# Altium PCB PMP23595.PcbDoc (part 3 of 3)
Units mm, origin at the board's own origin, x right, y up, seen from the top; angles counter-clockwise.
Board outline 121.92 x 78.74 mm, 6 copper layers (Layer 1, GND 1, Layer 3, Layer 4, GND 2, Layer 6), stack 2.208 mm thick; 236 components, 76 nets, 570 pads, 735 vias.
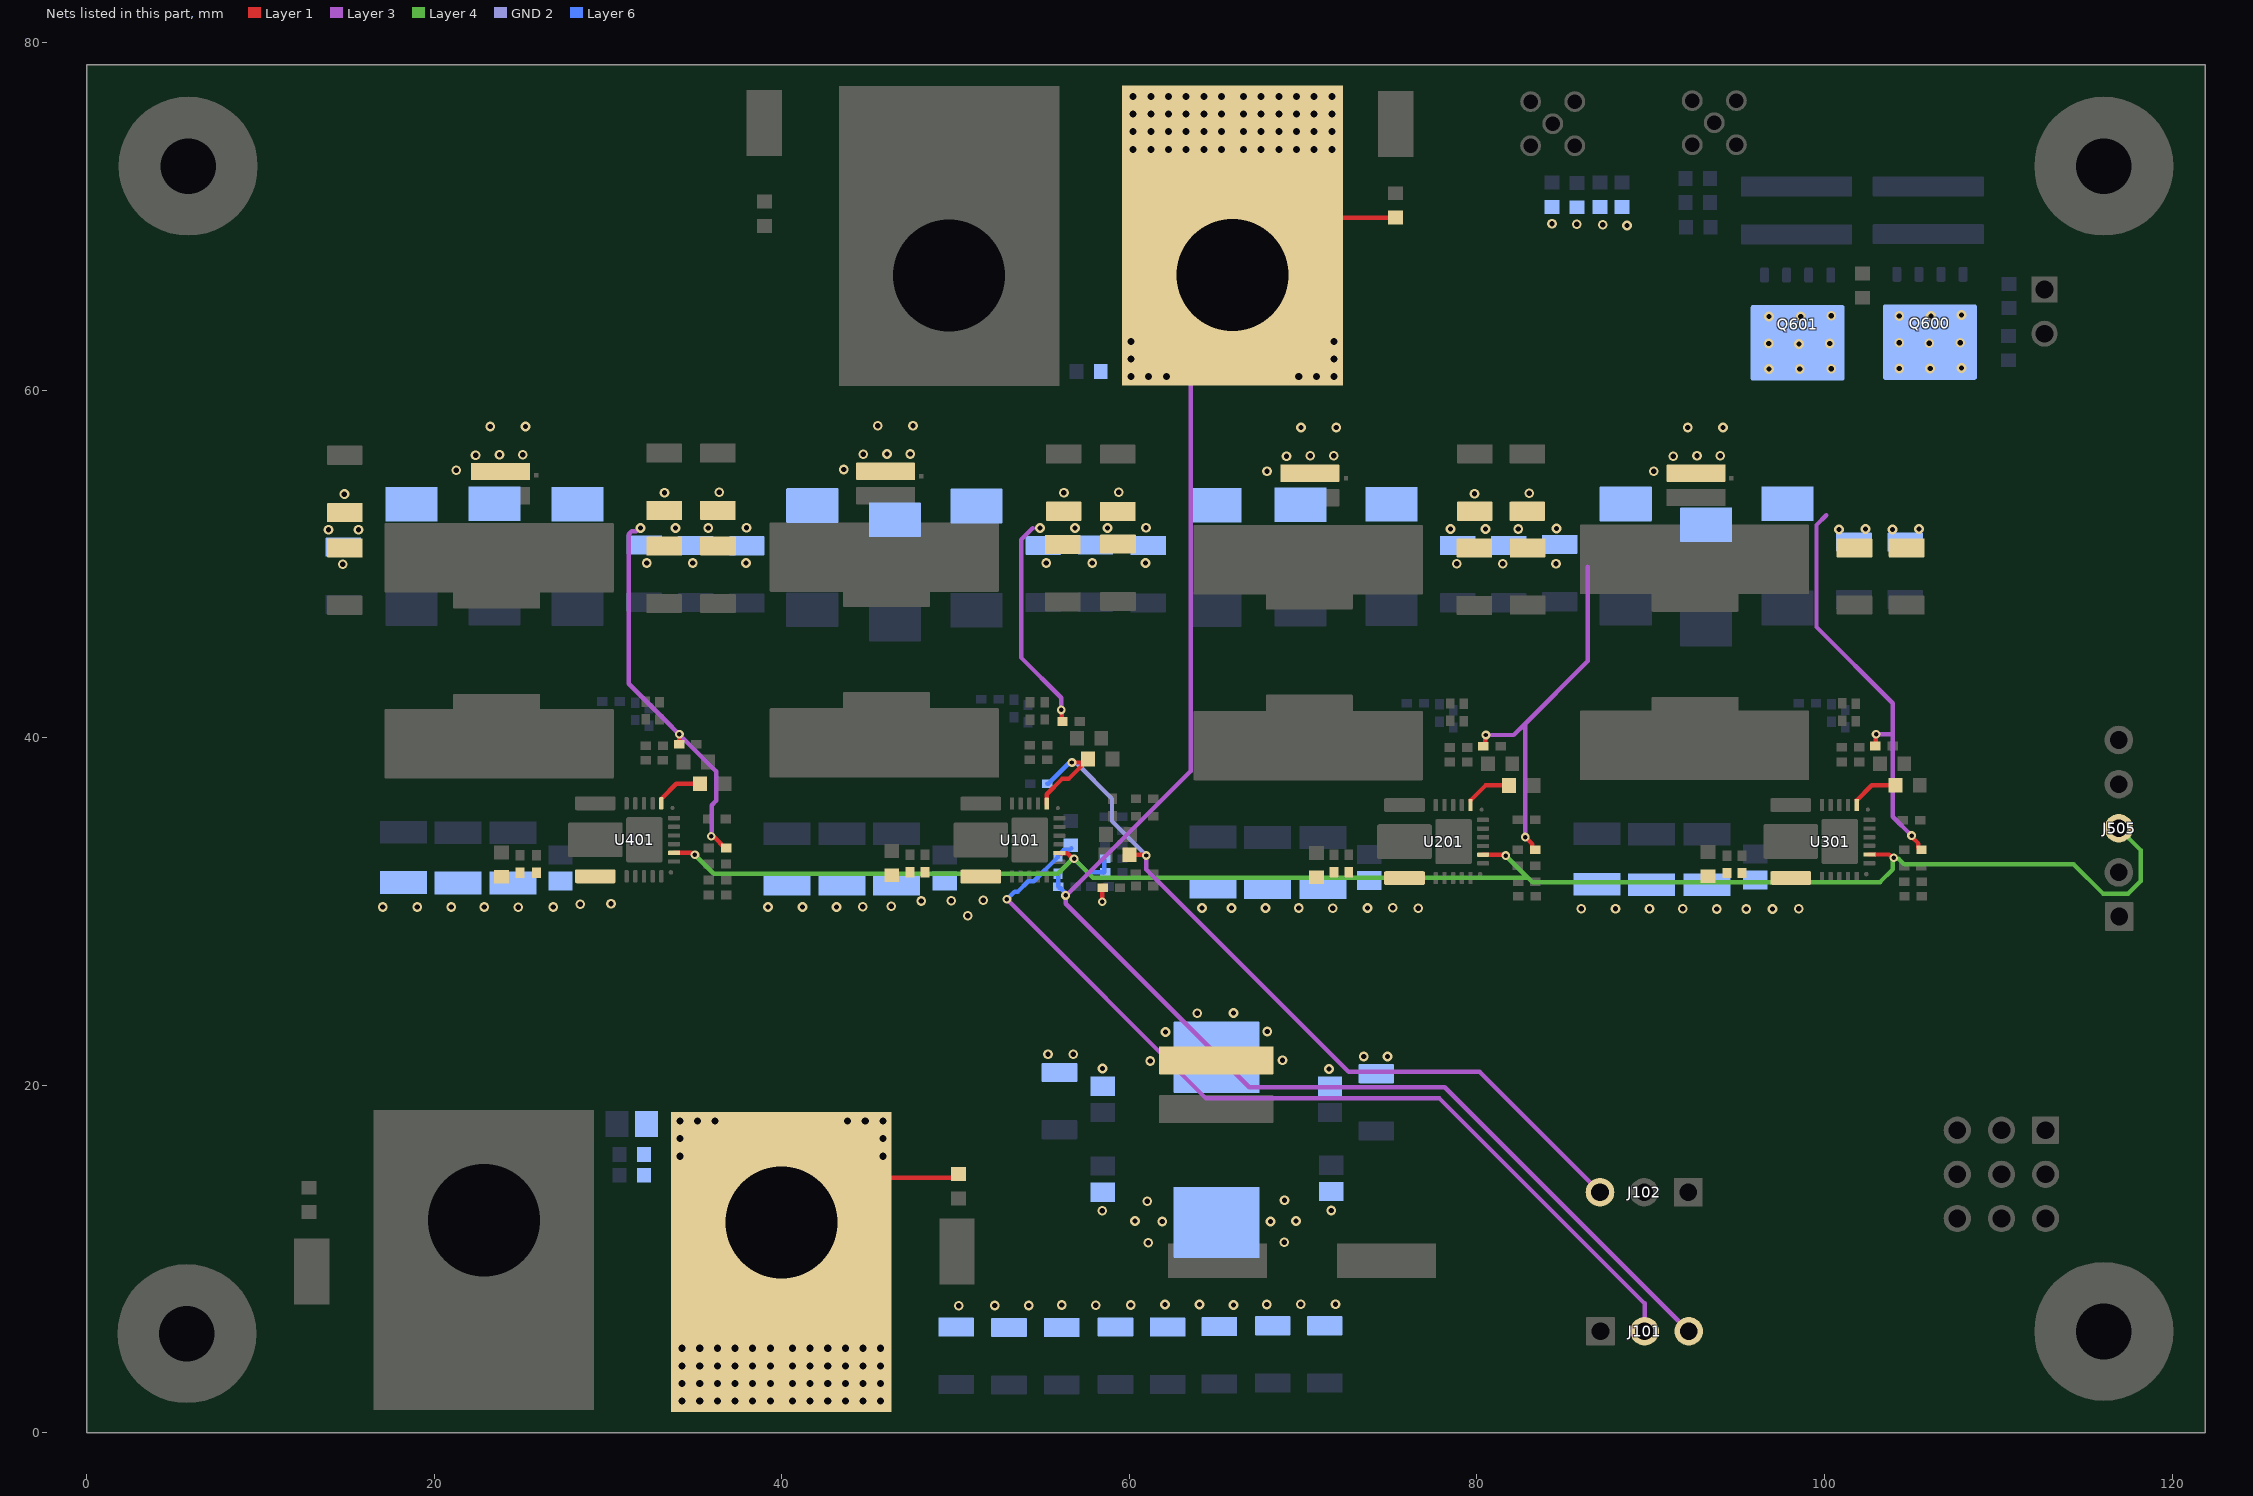
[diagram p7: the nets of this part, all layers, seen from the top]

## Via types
v1: diameter 0.559, hole 0.305, Layer 1 to Layer 6, tented both sides, 328 vias
v2: diameter 0.813, hole 0.406, Layer 1 to Layer 6, 232 vias
v3: diameter 0.508, hole 0.254, Layer 1 to Layer 6, tented both sides, 72 vias
v4: diameter 0.5, hole 0.2, Layer 1 to Layer 6, tented both sides, 72 vias
v5: diameter 0.559, hole 0.305, Layer 1 to Layer 6, 24 vias
v6: diameter 5.8, hole 2.8, Layer 1 to Layer 6, 7 vias

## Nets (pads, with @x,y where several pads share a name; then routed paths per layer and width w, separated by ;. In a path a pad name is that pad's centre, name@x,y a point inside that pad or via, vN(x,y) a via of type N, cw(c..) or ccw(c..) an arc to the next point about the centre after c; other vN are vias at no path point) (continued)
VBAT+: C500.2 C501.1 C502.1 C503.2 C504.2 C505.2 C506.2 C507.2 C508.2 C509.2 C510.2 C511.1 C512.1 L500.1 R500.2 T500.1 | length 9.7
  Layer 1 w0.254: T500.1@40.564,14.681 49.948,14.681 R500.2@50.165,14.899
  other v1: 50.188,7.32 52.254,7.338 54.21,7.338 58.075,7.352 56.115,7.363 60.077,7.363 65.995,7.363 62.058,7.388 64.04,7.388 67.9,7.388 69.86,7.403 71.863,7.414 61.085,10.953 68.91,10.973 61.898,12.172 68.121,12.172 60.323,12.197 69.594,12.197 58.443,12.781 71.626,12.807 61.034,13.34 68.933,13.391
  other v2: 34.265,1.829 35.281,1.829 36.297,1.829 37.313,1.829 38.329,1.829 39.345,1.829 40.615,1.829 41.631,1.829 42.647,1.829 43.663,1.829 44.679,1.829 45.695,1.829 34.265,2.845 35.281,2.845 36.297,2.845 37.313,2.845 38.329,2.845 39.345,2.845 40.615,2.845 41.631,2.845 42.647,2.845 43.663,2.845 44.679,2.845 45.695,2.845 34.265,3.861 35.281,3.861 36.297,3.861 37.313,3.861 38.329,3.861 39.345,3.861 40.615,3.861 41.631,3.861 42.647,3.861 43.663,3.861 44.679,3.861 45.695,3.861 34.265,4.877 35.281,4.877 36.297,4.877 37.313,4.877 38.329,4.877 39.345,4.877 40.615,4.877 41.631,4.877 42.647,4.877 43.663,4.877 44.679,4.877 45.695,4.877 34.138,15.926 45.822,15.926 34.138,16.942 45.822,16.942 34.138,17.958 35.154,17.958 36.17,17.958 43.79,17.958 44.806,17.958 45.822,17.958
VBODE: J101.2 R113.1 R119.2 | length 52.8
  Layer 3 w0.254: v3(52.959,30.709) 64.414,19.253 76.479,19.253 ; 76.505,19.253 77.851,19.253 89.649,7.455 J101.2@89.649,5.857
  Layer 6 w0.254: v3(52.959,30.709) 52.963,30.709 53.41,31.156 53.589,31.156 54.183,31.749 54.501,31.749 55.891,33.14 R113.1@55.891,33.19 ; R113.1@55.917,33.24 56.226,33.549 56.562,33.549 R119.2@56.667,33.655
VCC1: C110.1 J102.3 R107.2 R118.2 U101.2 | length 49.4
  Layer 1 w0.254: U101.2@55.25,36.22 55.25,36.758 56.127,37.636 56.503,37.636 C110.1@57.45,38.583 ; v3(56.693,38.583) C110.1@57.45,38.583 ; C110.1@57.506,38.557 57.48,38.583 C110.1@57.45,38.583 ; C110.1@57.633,38.79 57.633,38.765 C110.1@57.45,38.583 ; R118.2@60.02,33.269 60.856,33.269 60.935,33.19 v3@60.935,33.147
  Layer 3 w0.254: v3@60.96,33.172 60.973,33.159 60.973,32.424 72.62,20.777 80.161,20.777 J102.3@87.084,13.853
  GND 2 w0.254: v3(56.693,38.583) 56.741,38.534 56.97,38.534 59.004,36.5 59.004,35.197 v3(60.973,33.228) v3@60.985,33.215
  Layer 6 w0.254: R107.2@55.288,37.352 55.338,37.352 56.52,38.534 56.575,38.534 56.667,38.626 v3@56.667,38.684
VCC2: C210.1 U201.2 | length 2.6
  Layer 1 w0.254: U201.2@79.632,36.354 79.632,36.399 80.495,37.262 C210.1@81.853,37.262
VCC3: C310.1 U301.2 | length 2.6
  Layer 1 w0.254: U301.2@101.854,36.398 102.722,37.267 C310.1@104.081,37.267
VCC4: C410.1 U401.2 | length 2.6
  Layer 1 w0.254: U401.2@33.074,36.455 33.074,36.501 33.936,37.363 C410.1@35.295,37.363
VFILTER: C101.1 C102.1 C103.1 C104.1 C105.1 C106.1 C107.1 C201.1 C202.1 C203.1 C204.1 C205.1 C206.1 C207.1 C301.1 C302.1 C303.1 C304.1 C305.1 C306.1 C307.1 C401.1 C402.1 C403.1 C404.1 C405.1 C406.1 C407.1 C513.1 C514.1 C515.2 C516.2 L500.2 R111.2 R502.2 U101.9 U201.9 U301.9 U401.9 | length 0.9
  Layer 1 w0.254: v3@58.42,30.607 58.454,30.641 58.454,31.485 R111.2@58.465,31.496
  other v1: 71.486,20.946 58.456,20.972 61.199,21.403 68.819,21.454 73.482,21.666 74.854,21.666 55.321,21.793 56.769,21.793 62.088,23.08 67.93,23.105 63.917,24.147 65.999,24.172 50.698,29.769 85.998,30.162 87.979,30.162 89.935,30.162 91.84,30.162 93.8,30.151 95.504,30.15 97.005,30.15 98.524,30.162 64.18,30.213 65.881,30.213 67.837,30.213 69.742,30.213 71.702,30.202 73.705,30.213 76.631,30.201 75.156,30.226 24.844,30.26 39.211,30.264 41.193,30.264 43.148,30.264 17.043,30.271 19.024,30.271 20.98,30.271 22.885,30.271 26.847,30.271 44.653,30.277 46.304,30.302 28.398,30.421 30.175,30.459 48.031,30.607 49.759,30.632 51.587,30.658
  other v3: 58.443,30.567
VOUT: C111.1 C112.1 C113.1 C114.1 C115.1 C116.1 C117.1 C118.2 C119.2 C120.2 C211.1 C212.1 C213.1 C214.1 C215.1 C216.1 C217.1 C218.2 C219.2 C220.2 C311.1 C312.1 C313.1 C314.1 C315.1 C316.1 C317.1 C318.2 C319.2 C320.2 C411.1 C412.1 C413.1 C414.1 C415.1 C416.1 C417.1 C418.2 C419.2 C420.2 C518.1 C600.1 C601.2 C603.2 J101.3 NT21.2 NT31.2 NT41.2 NT101.2 Q600.5 Q600.6 Q600.7 Q600.8 Q600.9@106.07,62.773 Q601.5 Q601.6 Q601.7 Q601.8 Q601.9@98.456,62.73 R101.2 R103.2 R108.2 R113.2 R201.2 R203.2 R207.2 R301.2 R303.2 R307.2 R401.2 R403.2 R407.2 R501.1 R604.2 T501.1 | length 175.7
  Layer 1 w0.254: R403.2@34.036,39.649 34.102,39.716 34.102,40.198 v3(34.112,40.208) ; v3(35.941,34.341) 35.99,34.292 36.112,34.292 36.724,33.681 R407.2@36.804,33.681 ; R103.2@56.058,40.869 R103.2@56.058,40.894 ; R103.2@56.083,40.97 56.118,41.005 56.118,41.57 v3(56.083,41.605) ; R103.2@56.153,40.94 R103.2@56.203,40.94 ; T501.1@66.065,67.31 68.693,69.937 R501.1@75.311,69.937 R501.1@75.549,69.937 ; R203.2@80.467,39.548 80.472,39.552 80.472,40.117 v3(80.52,40.165) ; v3(82.779,34.29) 83.182,33.887 83.182,33.679 83.282,33.579 R207.2@83.363,33.579 ; R303.2@102.972,39.548 102.95,39.569 102.95,40.187 v3(102.972,40.208) ; v3(105.014,34.376) 105.014,34.307 105.407,33.914 105.407,33.687 105.515,33.579 R307.2@105.588,33.579
  Layer 3 w0.254: v1(31.877,52.07) 31.795,52.07 31.623,51.898 31.371,51.898 31.191,51.718 31.191,43.113 36.22,38.084 36.22,36.374 35.966,36.12 35.966,34.366 v3(35.941,34.341) ; 54.432,52.065 53.772,51.404 53.772,44.622 56.083,42.311 v3(56.083,41.605) v3@56.109,41.58 ; T501.1@65.405,64.973 63.525,63.094 63.525,38.08 56.382,30.937 v3(56.337,30.937) 56.337,30.45 66.899,19.888 78.158,19.888 J101.3@92.189,5.857 ; v3(80.52,40.165) 82.126,40.165 82.779,40.818 ; v3(82.779,34.29) 82.779,40.076 ; 82.779,40.081 82.779,40.818 ; 86.385,49.835 86.385,44.425 82.779,40.818 ; 100.101,52.807 99.543,52.248 99.543,46.38 103.935,41.988 103.935,40.208 103.935,35.454 v3(105.014,34.376) ; v3(102.972,40.208) 103.861,40.208 103.886,40.234
  Layer 6 w0.254: R113.2@55.887,32.087 R113.2@55.982,32.182 ; R108.2@55.909,31.434 55.913,31.438 R113.2@55.913,32.087 ; R108.2@55.956,31.369 56.024,31.369 56.289,31.104 56.289,30.986 v3(56.337,30.937)
  other v1: 14.732,49.987 78.842,50.013 81.483,50.013 84.557,50.013 32.233,50.063 34.874,50.063 37.948,50.063 55.22,50.063 57.861,50.063 60.935,50.063 13.919,51.968 15.646,51.968 100.838,51.994 103.911,51.994 78.486,52.019 80.493,52.019 82.372,52.019 102.362,52.019 105.435,52.019 84.582,52.045 33.884,52.07 35.763,52.07 54.864,52.07 56.871,52.07 58.75,52.07 37.973,52.095 60.96,52.095 14.834,54.026 79.858,54.051 83.007,54.077 33.249,54.102 56.236,54.102 36.398,54.127 59.385,54.127 67.926,55.346 90.176,55.346 21.266,55.397 43.567,55.447 69.043,56.209 91.294,56.209 70.415,56.235 71.761,56.235 92.665,56.235 94.012,56.235 22.384,56.26 23.755,56.286 25.101,56.286 44.685,56.311 46.056,56.336 47.403,56.336 69.882,57.86 71.914,57.86 92.132,57.86 94.164,57.86 23.222,57.911 25.254,57.911 45.523,57.962 47.555,57.962 88.643,69.479 87.246,69.53 85.747,69.556 84.32,69.581
  other v2: 60.096,60.782 61.112,60.782 62.128,60.782 69.748,60.782 70.764,60.782 71.78,60.782 60.096,61.798 71.78,61.798 60.096,62.814 71.78,62.814 60.223,73.863 61.239,73.863 62.255,73.863 63.271,73.863 64.287,73.863 65.303,73.863 66.573,73.863 67.589,73.863 68.605,73.863 69.621,73.863 70.637,73.863 71.653,73.863 60.223,74.879 61.239,74.879 62.255,74.879 63.271,74.879 64.287,74.879 65.303,74.879 66.573,74.879 67.589,74.879 68.605,74.879 69.621,74.879 70.637,74.879 71.653,74.879 60.223,75.895 61.239,75.895 62.255,75.895 63.271,75.895 64.287,75.895 65.303,75.895 66.573,75.895 67.589,75.895 68.605,75.895 69.621,75.895 70.637,75.895 71.653,75.895 60.223,76.911 61.239,76.911 62.255,76.911 63.271,76.911 64.287,76.911 65.303,76.911 66.573,76.911 67.589,76.911 68.605,76.911 69.621,76.911 70.637,76.911 71.653,76.911
  other v5: 96.805,61.219 98.583,61.219 100.386,61.245 104.301,61.257 106.079,61.257 107.883,61.283 98.532,62.667 96.799,62.696 100.31,62.693 106.028,62.705 104.296,62.734 107.806,62.73 96.805,64.242 98.633,64.242 100.386,64.293 104.301,64.28 106.13,64.28 107.883,64.331
VSET: C126.1 J505.3 R121.2 U101.17 U201.17 U301.17 U401.17 | length 100
  Layer 1 w0.254: U401.17@33.797,33.382 34.824,33.382 34.932,33.274 v3(35.001,33.274) ; U101.17@55.975,33.37 55.977,33.368 56.428,33.368 56.751,33.045 v3(56.82,33.045) ; U201.17@80.358,33.278 81.537,33.278 81.592,33.223 v3(81.661,33.223) ; U301.17@102.583,33.285 103.73,33.285 103.919,33.096 v3(103.988,33.096)
  Layer 4 w0.254: v3(35.001,33.274) 36.093,32.182 55.887,32.182 56.751,33.045 v3(56.82,33.045) ; v3@56.845,33.02 57.912,31.953 82.906,31.953 ; v3(81.661,33.223) 82.787,32.097 ; 82.787,31.987 82.787,32.097 ; J505.3@116.939,34.798 118.189,33.548 118.189,31.753 117.475,31.039 116.027,31.039 114.351,32.715 104.597,32.715 104.265,33.048 104.036,33.048 v3(103.988,33.096) 103.939,33.048 103.939,32.438 103.2,31.699 83.185,31.699 82.787,32.097
  Layer 6 w0.254: v3(56.82,33.045) 56.82,33.038 57.599,32.258 C126.1@58.547,32.258 ; C126.1@58.522,32.233 C126.1@58.547,32.258 ; C126.1@58.555,32.258 C126.1@58.547,32.258 ; R121.2@58.555,33.045 58.555,32.266 C126.1@58.547,32.258
pads on no net: H704.0 H705.0 H706.0 H707.0 Q600.9@103.698,64.683 Q600.9@104.74,62.088 Q600.9@104.74,63.238 Q600.9@104.74,64.388 Q600.9@106.07,62.088 Q600.9@106.07,63.103 Q600.9@106.07,63.238 Q600.9@106.07,64.388 Q600.9@107.4,62.088 Q600.9@107.4,63.238 Q600.9@107.4,64.388 Q600.9@108.443,64.683 Q601.9@96.083,64.64 Q601.9@97.126,62.045 Q601.9@97.126,63.195 Q601.9@97.126,64.345 Q601.9@98.456,62.045 Q601.9@98.456,63.06 Q601.9@98.456,63.195 Q601.9@98.456,64.345 Q601.9@99.786,62.045 Q601.9@99.786,63.195 Q601.9@99.786,64.345 Q601.9@100.828,64.64 U101.10 U201.10 U301.10 U401.10

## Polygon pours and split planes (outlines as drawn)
GND on Layer 1 "LAYER_1_GND_P095" (solid, remove dead copper, pour order 95): 1.524,1.118 1.524,77.749 120.32,77.778 120.32,1.118
VOUT on Layer 1 "LAYER_6_VOUT_P091" (solid, remove dead copper, pour order 93): 89.23,65.735 89.23,71.095 79.629,71.095 79.629,77.775 57.201,77.774 57.201,60.401 56.439,59.639 14.681,59.639 12.471,57.429 12.471,50.19 13.106,49.555 108.306,49.555 109.372,50.622 109.372,65.735
NetL401_2 on Layer 1 "LAYER_1_NETL401_2_P040" (solid, remove dead copper, pour order 40): 30.658,52.603 30.658,52.664 28.829,54.559 19.024,54.559 18.781,54.493 16.891,52.603 16.891,47.371 30.658,47.371
NetL301_2 on Layer 1 "LAYER_1_NETL301_2_P032" (solid, remove dead copper, pour order 32): 99.392,52.603 99.392,52.628 97.657,54.366 87.387,54.366 85.625,52.603 85.625,47.178 99.392,47.178
NetL201_2 on Layer 1 "LAYER_1_NETL201_2_P030" (solid, remove dead copper, pour order 30): 77.167,52.675 75.45,54.391 65.303,54.391 65.162,54.366 63.4,52.603 63.4,47.203 77.167,47.203
NetL101_2 on Layer 1 "LAYER_1_NETL101_2_P029" (solid, remove dead copper, pour order 29): 52.808,52.603 52.808,52.675 51.012,54.493 40.909,54.493 40.909,54.471 39.041,52.603 39.041,47.305 52.808,47.305
NetC517_1 on Layer 1 "LAYER_1_NETC517_1_P069" (solid, pour order 69): 68.351,19.482 61.646,19.482 61.646,8.763 68.351,8.763
GND on Layer 1 "LAYER_1_GND_P000" (solid, pour order 0): 77.841,57.718 85.072,57.718 85.072,55.661 77.841,55.661
GND on Layer 1 "LAYER_1_GND_P005" (solid, pour order 5): 54.27,57.642 61.501,57.642 61.501,55.585 54.27,55.585
GND on Layer 1 "LAYER_1_GND_P006" (solid, pour order 6): 31.124,57.773 38.354,57.773 38.354,55.715 31.124,55.715
GND on Layer 1 "LAYER_1_GND_P028" (solid, pour order 28): 12.878,57.76 16.586,57.76 16.586,55.702 12.878,55.702
AGND3 on Layer 1 "LAYER_1_AGND3_P078" (solid, remove dead copper, pour order 78): 106.096,35.738 106.299,35.535 106.299,33.198 106.02,32.918 105.258,32.918 105.258,30.607 106.02,30.607 106.02,31.953 107.239,33.172 107.239,36.652 106.197,37.694 105.054,37.694 105.054,36.83 104.699,36.474 102.235,36.474 102.235,35.738
AGND2 on Layer 1 "LAYER_1_AGND2_P077" (solid, remove dead copper, pour order 77): 83.871,35.738 84.074,35.535 84.074,33.198 83.795,32.918 83.033,32.918 83.033,30.607 83.693,30.607 83.693,31.852 85.014,33.172 85.014,36.652 83.972,37.694 82.829,37.694 82.829,36.83 82.474,36.474 80.01,36.474 80.01,35.738
SW on Layer 1 "LAYER_1_SW_P087" (solid, remove dead copper, pour order 87): 50,35.7 52.718,35.7 52.718,41.593 52.515,41.796 39.408,41.796 39.154,41.542 39.154,37.757 39.484,37.427 48.273,37.427
SW2 on Layer 1 "LAYER_1_SW2_P088" (solid, remove dead copper, pour order 88): 74.384,35.649 77.102,35.649 77.102,41.542 76.899,41.745 63.792,41.745 63.538,41.491 63.538,37.706 63.868,37.376 72.657,37.376
SW3 on Layer 1 "LAYER_1_SW3_P090" (solid, remove dead copper, pour order 90): 96.66,35.624 99.378,35.624 99.378,41.516 99.174,41.72 86.068,41.72 85.814,41.466 85.814,37.681 86.144,37.351 94.933,37.351
AGND4 on Layer 1 "LAYER_1_AGND4_P081" (solid, remove dead copper, pour order 81): 37.313,35.839 37.516,35.636 37.516,33.299 37.236,33.02 36.474,33.02 36.474,30.658 37.109,30.658 37.109,31.928 38.456,33.274 38.456,36.754 37.414,37.795 36.271,37.795 36.271,36.932 35.916,36.576 33.452,36.576 33.452,35.839
VFILTER on Layer 1 "LAYER_1_VFILTER_P082" (solid, pour order 82): 15.418,32.588 99.492,32.588 99.492,20.396 15.418,20.396
AGND1 on Layer 1 "LAYER_1_AGND1_P083" (solid, pour order 83): 61.036,35.103 60.833,34.9 59.639,34.9 59.639,33.96 60.808,33.96 61.036,33.731 61.036,31.267 61.138,31.166 62.078,31.166 62.357,31.445 62.357,37.084 60.223,39.218 58.572,39.218 58.572,38.405 56.744,36.576 55.626,36.576 55.626,35.814 57.277,35.814 58.522,37.059 60.858,37.059 61.036,36.881
SW4 on Layer 1 "LAYER_1_SW4_P091" (solid, remove dead copper, pour order 91): 27.838,35.763 30.556,35.763 30.556,41.656 30.353,41.859 17.247,41.859 16.993,41.605 16.993,37.821 17.323,37.49 26.111,37.49
GND on Layer 3 "LAYER_3_GND_P094" (solid, remove dead copper, pour order 94): 1.524,1.118 1.524,77.749 120.32,77.778 120.32,1.118
VOUT on Layer 3 "LAYER_6_VOUT_P091" (solid, remove dead copper, pour order 18): 89.23,65.735 89.23,71.095 79.629,71.095 79.629,77.775 57.201,77.774 57.201,60.401 56.439,59.639 14.681,59.639 12.471,57.429 12.471,50.19 13.106,49.555 108.306,49.555 109.372,50.622 109.372,65.735
VBAT+ on Layer 3 "LAYER_3_VBAT+_P080" (solid, pour order 80): 33.223,19.025 33.223,14.351 33.223,1.118 46.685,1.118 46.685,4.851 72.72,4.851 72.72,14.529 46.99,14.529 46.99,19.025
GND on Layer 6 "LAYER_6_GND_P102" (solid, remove dead copper, pour order 102): 1.524,1.13 120.32,1.13 120.32,77.816 1.524,77.787
VOUT on Layer 6 "LAYER_6_VOUT_P091" (solid, remove dead copper, pour order 97): 89.23,65.735 89.23,71.095 79.629,71.095 79.629,77.775 57.201,77.774 57.201,60.401 56.439,59.639 14.681,59.639 12.471,57.429 12.471,50.19 13.106,49.555 108.306,49.555 109.372,50.622 109.372,65.735
NetQ600_1 on Layer 6 "LAYER_6_NETQ600_1_P098" (solid, pour order 98): 107.194,66.044 103.649,66.044 103.649,67.442 99.607,67.442 99.607,66.044 94.948,66.044 94.948,69.909 109.451,69.909 109.451,67.442 107.194,67.442
VBAT+ on Layer 6 "LAYER_6_VBAT+_P099" (solid, pour order 99): 31.547,19.025 31.547,14.351 33.223,14.351 33.223,1.118 46.685,1.118 46.685,4.851 72.72,4.851 72.72,14.529 46.99,14.529 46.99,19.025
AGND1 on Layer 6 "LAYER_6_AGND1_P100" (solid, remove dead copper, pour order 100): 56.109,36.576 56.769,36.576 57.506,37.313 60.071,37.313 60.325,37.059 60.325,31.14 58.474,31.14 58.474,32.537 59.03,32.537 59.258,32.766 59.258,35.662 59.03,35.89 56.109,35.89
VFILTER on Layer 6 "LAYER_6_VFILTER_P101" (solid, pour order 101): 97.206,27.968 97.258,28.02 97.258,29.667 99.251,29.667 99.293,29.71 99.293,32.407 97.183,32.407 97.18,32.41 16.383,32.41 16.383,19.279 97.206,19.279
GND on Layer 4 "LAYER_4_GND_P084" (solid, remove dead copper, pour order 84): 1.524,1.118 1.524,77.749 120.32,77.778 120.32,1.118
VBAT+ on Layer 4 "LAYER_4_VBAT+_P085" (solid, pour order 85): 65.049,20.371 65.049,16.891 65.049,1.09 31.699,1.09 31.699,24.536 65.049,24.536
GND on GND 2 "GND_2_GND_P056" (solid, remove dead copper, pour order 56): 1.524,1.118 1.524,77.749 120.32,77.778 120.32,1.118
GND on GND 1 "GND_1_GND_P060" (solid, remove dead copper, pour order 60): 1.524,1.118 1.524,77.749 120.32,77.778 120.32,1.118

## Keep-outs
Layer 1:
  rectangle: 38.594,69.038 43.256,69.825
  rectangle: 12.381,13.686 17.486,14.473
  rectangle: 72.288,69.545 75.733,70.333
Keep-Out Layer:
  text ".Layer_Name" at 12.116,-19.367 h1.52

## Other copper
Layer 1:
  text ".Layer_Name" at 12.116,-19.367 h1.52
Layer 6:
  text ".Layer_Name" at 12.116,-19.367 h1.52

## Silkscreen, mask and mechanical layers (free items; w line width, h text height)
Top Overlay:
  lines w0.254: 6.604,20.803 113.792,20.803 113.792,47.803 6.604,47.803 6.604,20.803 ; 13.385,30.375 106.197,30.375 106.197,57.248 13.385,57.248 13.385,30.375
  text "VOUT" at 82.399,70.35 h1.52
  text "IOUT" at 92.354,70.35 h1.52
  text "'.PRJ_Number'.PCB_Rev" at 17.399,67.843 h2.75
  text "Gate" at 116.086,65.137 h1.52 r90
  text "GND" at 116.086,61.151 h1.52 r90
  text "PGOOD" at 119.717,40.196 h1.52 r90
  text "ISET" at 120.9,36.921 h1.52 r90
  text "VSET" at 119.649,33.093 h1.52 r90
  text "IMON" at 120.9,29.611 h1.52 r90
  text "GND" at 119.7,26.545 h1.52 r90
  text "PH1" at 102.438,17.023 h1.52
  text "VCC1" at 85.218,15.765 h1.52
  text "GND" at 90.805,15.714 h1.52
  text "PH3" at 102.777,13.691 h1.52 r90
  text "PH4" at 101.016,13.64 h1.52 r90
  text "PH2" at 104.724,13.64 h1.52 r90
  text "GND" at 102.006,11.599 h1.52
  text "FPWM/" at 87.884,11.066 h1.52
  text "EN/UVLO selector" at 117.585,11.009 h1.52 r90
  text "SYNC 1" at 87.757,9.618 h1.52
  text "VBODE" at 87.377,3.04 h1.52
  text "VOUT" at 90.933,1.49 h1.52
  text "GND" at 85.75,1.389 h1.52
  text ".Layer_Name" at 12.116,-19.367 h1.52
Bottom Overlay:
  lines w0.254: 13.386,30.378 106.197,30.378 106.197,57.252 13.386,57.252 13.386,30.378
  text ".Layer_Name" at 12.116,-19.367 h1.52
Top Paste:
  text ".Layer_Name" at 12.116,-19.367 h1.52
Bottom Paste:
  text ".Layer_Name" at 12.116,-19.367 h1.52
Top Solder:
  text ".Layer_Name" at 12.116,-19.367 h1.52
  text ".Layer_Name" at 12.116,-19.367 h1.52
Bottom Solder:
  text ".Layer_Name" at 12.116,-19.367 h1.52
Drill Guide:
  text ".Layer_Name" at 12.116,-19.367 h1.52
M1 Board Outline:
  the board outline again, w0.254
  text ".Layer_Name" at 12.116,-19.367 h1.52
M2 Board Dimensions:
  rectangle: -2.54,-4.547 0.635,-1.372
  rectangle: 0.635,-7.722 10.16,-4.547
  lines w0.178: -2.54,-4.547 22.86,-4.547 ; -2.54,-1.372 -2.54,-7.722 22.86,-7.722 22.86,-1.372 ; 0.635,-7.722 0.635,-1.372 ; 3.81,-7.722 3.81,-1.372 ; 10.16,-7.722 10.16,-1.372 ; 11.938,-1.27 37.338,-1.27 ; 16.51,-7.722 16.51,-1.372
  text ".Layer_Name" at 12.116,-19.367 h1.52
M3 3D STEP Top:
  text ".Layer_Name" at 12.116,-19.367 h1.52
M4 3D STEP Bottom:
  text ".Layer_Name" at 12.116,-19.367 h1.52
M5 Assembly Top:
  lines w0.254: -9.957,-21.188 157.683,-21.188 ; -9.957,-16.023 157.734,-16.023 ; -9.957,-10.858 -9.957,-26.352 91.77,-26.352 157.734,-26.352 157.734,-10.859 -9.944,-10.859 -9.944,-26.352 30.074,-26.352 ; 52.654,-26.352 52.654,-10.859 ; 84.836,-16.023 84.836,-10.859 ; 106.172,-16.023 106.172,-10.859 ; 121.971,-26.518 121.971,-21.366
  text "COMPONENTS MARKED 'DNP' SHOULD NOT BE POPULATED." at 26.759,-5.651 h1.52
  text "ASSEMBLY VARIANT:" at 26.746,-8.585 h1.52
  text ".VariantName" at 53.061,-8.585 h1.52
  text "PCB VIEWED FROM TOP SIDE" at -8.344,-14.216 h1.52
  text "BOARD #:" at 54.559,-14.216 h1.52
  text ".PRJ_Number" at 68.415,-14.216 h1.52
  text "REV:" at 89.865,-14.216 h1.52
  text ".PCB_Rev" at 97.269,-14.216 h1.52
  text "SVN REV:" at 111.15,-14.216 h1.52
  text ".VersionControl_RevNumber" at 124.003,-14.216 h1.52
  text "TID #:" at 54.559,-19.38 h1.52
  text ".TID" at 68.415,-19.38 h1.52
  text "PLOT NAME =" at -8.344,-24.596 h1.52
  text ".plot_File_Name" at 12.116,-24.596 h1.52
  text "GENERATED    :" at 54.61,-24.596 h1.52
  text ".Print_Date" at 76.695,-24.596 h1.52
  text ".Print_Time" at 95.212,-24.596 h1.52
  text "TEXAS INSTRUMENTS" at 127.33,-24.596 h1.52
M6 Assembly Bottom:
  lines w0.254: -9.97,-16.036 157.721,-16.036 ; -9.919,-21.201 157.721,-21.201 ; 25.794,-26.53 25.794,-21.378 ; 41.593,-16.036 41.593,-10.871 ; 62.928,-16.036 62.928,-10.871 ; 95.11,-26.365 95.11,-10.871 ; 117.691,-26.365 157.709,-26.365 157.709,-10.871 -9.97,-10.871 -9.97,-26.365 55.994,-26.365 157.721,-26.365 157.721,-10.871
  text "COMPONENTS MARKED 'DNP' SHOULD NOT BE POPULATED." at 152.451,-5.639 h1.52
  text ".VariantName" at 125.933,-8.585 h1.52
  text "ASSEMBLY VARIANT:" at 152.324,-8.585 h1.52
  text ".VersionControl_RevNumber" at 23.762,-14.228 h1.52
  text "SVN REV:" at 36.614,-14.228 h1.52
  text ".PCB_Rev" at 50.495,-14.228 h1.52
  text "REV:" at 57.899,-14.228 h1.52
  text ".PRJ_Number" at 79.35,-14.228 h1.52
  text "BOARD #:" at 93.205,-14.228 h1.52
  text "PCB VIEWED FROM BOTTOM SIDE" at 156.108,-14.228 h1.52
  text ".TID" at 79.35,-19.393 h1.52
  text "TID #:" at 93.205,-19.393 h1.52
  text "TEXAS INSTRUMENTS" at 20.434,-24.608 h1.52
  text ".Print_Time" at 52.553,-24.608 h1.52
  text ".Print_Date" at 71.069,-24.608 h1.52
  text "GENERATED    :" at 93.154,-24.608 h1.52
  text ".plot_File_Name" at 135.649,-24.608 h1.52
  text "PLOT NAME =" at 156.108,-24.608 h1.52
M9 Title Sheet:
  drawing of 57 lines, arcs and shapes, not listed
  text "1" at 16.252,206.565 h1.78
  text "2" at 79.642,206.565 h1.78
  text "3" at 142.871,206.565 h1.78
  text "4" at 206.54,206.565 h1.78
  text "5" at 270.015,206.565 h1.78
  text "6" at 333.642,206.565 h1.78
  text "A" at -13.119,177.533 h1.78
  text "A" at 362.801,177.533 h1.78
  text "B" at -13.119,117.081 h1.78
  text "B" at 362.801,117.081 h1.78
  text "C" at -13.119,56.756 h1.78
  text "C" at 362.801,56.756 h1.78
  text "PROJECT TITLE:" at 285.585,9.487 h1.14
  text ".PRJ_Title" at 286.855,6.1 h1.78
  text "DESIGNED FOR:" at 285.585,1.841 h1.14
  text ".PRJ_Customer" at 286.855,-1.714 h1.78
  text "D" at -13.119,-3.442 h1.78
  text "D" at 362.801,-3.442 h1.78
  text "FILE NAME:" at 285.585,-5.779 h1.14
  text ".PCB_File_Name_No_Path" at 286.855,-8.826 h1.78
  text "Texas Instruments (TI) and/or its licensors do not warrant the accuracy or completeness of this specification" at 159.36,-12.937 h1.14
  text "ENGINEER:" at 285.585,-13.144 h1.14
  text "LAYOUT BY:" at 323.812,-13.144 h1.14
  text "or any information contained therein. TI and/or its licensors do not warrant that this design will meet" at 158.217,-15.799 h1.14
  text ".PRJ_Engineer" at 286.855,-17.081 h1.78
  text ".PCB_Layout" at 325.095,-17.081 h1.78
  text "the specifications, will be suitable for your application or fit for any particular purpose, or will operate in" at 158.217,-18.661 h1.14
  text ".Layer_Name" at 12.116,-19.367 h1.52
  text "ALTIUM DESIGNER VERSION:" at 323.812,-21.018 h1.14
  text "an implementation. TI and/or its licensors do not warrant that the design is production worthy. You should" at 158.217,-21.522 h1.14
  text "completely validate and test your design implementation to confirm the system functionality for your application." at 159.36,-24.384 h1.14
  text ".print_Scale" at 286.855,-24.405 h1.78
  text ".Application_BuildNumber" at 325.095,-24.405 h1.78
  text "1" at 16.252,-29.654 h1.78
  text "2" at 79.642,-29.654 h1.78
  text "3" at 142.871,-29.654 h1.78
  text "4" at 206.54,-29.654 h1.78
  text "5" at 270.015,-29.654 h1.78
  text "6" at 333.642,-29.654 h1.78
M10 Fab Notes:
  drawing of 189 lines, arcs and shapes, not listed
  text "DESIGN INFORMATION" at 311.963,163.885 h1.52
  text "MIN. TRACK WIDTH:" at 295.591,160.529 h1.52
  text "8" at 323.436,160.529 h1.52
  text "MIL" at 327.367,160.529 h1.52
  text "7.874" at 319.21,157.438 h1.52
  text "MIN. CLEARANCE:" at 295.591,157.376 h1.52
  text "MIL" at 327.367,157.376 h1.52
  text "MIN. VIA PAD SIZE:" at 295.591,154.224 h1.52
  text "24" at 322.674,154.224 h1.52
  text "MIL" at 327.367,154.224 h1.52
  text "0.05mm (2MIL)" at 313.244,150.924 h1.52
  text "MINIMUM ANNULAR RING" at 287.229,150.715 h1.52
  text "EXTERNAL" at 331.228,150.715 h1.52
  text "PER" at 292.309,147.918 h1.52
  text "IPC-D-275 CLASS 2 LEVEL C" at 297.897,147.918 h1.52
  text "MIL, HOLES" at 335.698,145.366 h1.52
  text "+/-" at 325.73,145.148 h1.52
  text "+/-" at 347.421,145.148 h1.52
  text "REGISTRATION TOLERANCES:" at 287.229,145.121 h1.52
  text "METAL" at 317.703,145.121 h1.52
  text "5" at 332.339,145.121 h1.52
  text "3" at 353.497,145.121 h1.52
  text "MIL" at 356.45,145.121 h1.52
  text "HOLE SIZE TOLERANCE (UNLESS OTHERWISE SPECIFIED):" at 287.229,142.624 h1.52
  text "+/-" at 347.421,142.551 h1.52
  text "3" at 353.497,142.524 h1.52
  text "MIL" at 356.45,142.524 h1.52
  text "MATERIAL:" at 285.33,139.027 h1.52
  text "FR-4 High Tg" at 310.386,135.763 h1.52
  text "X" at 306.717,135.56 h1.52
  text "FR-4" at 296.023,135.445 h1.52
  text "OTHER" at 333.818,135.445 h1.52
  text "62 MIL (1.6mm) +/-10%" at 304.154,131.812 h1.52
  text "X" at 301.103,131.75 h1.52
  text "THICKNESS:" at 287.229,131.603 h1.52
  text "OTHER" at 336.79,131.603 h1.52
  text "TOLERANCE:" at 287.229,128.09 h1.52
  text "X" at 308.774,128.09 h1.52
  text "ANSI IPC-6012 TYPE 3 CLASS 2" at 313.296,128.09 h1.52
  text "OTHER +/-" at 313.295,124.428 h1.52
  text "BOW & TWIST:" at 287.229,120.74 h1.52
  text "X" at 308.774,120.74 h1.52
  text "ANSI IPC-6012 TYPE 3 CLASS 2" at 313.296,120.74 h1.52
  text "OTHER +/-" at 313.295,117.014 h1.52
  text "DRILLING:" at 285.33,113.696 h1.52
  text "NC_DRILL FILES" at 330.059,111.024 h1.52
  text "REFERENCE:" at 287.229,110.924 h1.52
  text "X" at 303.923,110.922 h1.52
  text "AS SHOWN" at 308.444,110.924 h1.52
  text "X" at 326.808,110.924 h1.52
  text "OTHER" at 337.628,107.311 h1.52
  text "PTH COPPER THICKNESS:" at 287.221,107.222 h1.52
  text "X" at 316.157,107.222 h1.52
  text "20-30 um" at 319.408,107.222 h1.52
  text "BOARD FINISH:" at 285.33,103.473 h1.52
  text "SILKSCREEN:" at 289.272,100.675 h1.52
  text "X" at 313.6,100.675 h1.52
  text "TOP" at 316.572,100.675 h1.52
  text "X" at 326.554,100.675 h1.52
  text "BOTTOM" at 329.551,100.675 h1.52
  text "SILKSCREEN COLOR:" at 289.272,96.734 h1.52
  text "X" at 313.575,96.734 h1.52
  text "WHITE" at 316.572,96.734 h1.52
  text "OTHER" at 329.551,96.734 h1.52
  text "X" at 316.902,93.09 h1.52
  text "GREEN" at 319.899,93.09 h1.52
  text "OTHER" at 335.596,93.09 h1.52
  text "SOLDER RESIST COLOR:" at 289.272,92.916 h1.52
  text "X" at 316.902,89.172 h1.52
  text "MATTE" at 319.899,89.172 h1.52
  text "SEMI-GLOSS" at 335.585,89.156 h1.52
  text "IMMERSION GOLD (ENIG)" at 312.279,84.784 h1.52
  text "ENEPIG" at 346.253,84.6 h1.52
  text "SURFACE FINISH:" at 285.33,84.575 h1.52
  text "X" at 307.758,84.575 h1.52
  text "IMM. TIN/SILVER OR EQUIV" at 293.7,81.087 h1.52
  text "OTHER" at 330.059,80.987 h1.52
  text "ARRAY/PANEL:" at 285.33,77.04 h1.52
  text "CUT AND TRIM PER M1 BOARD OUTLINE" at 312.279,76.832 h1.52
  text "N.C. ROUTE" at 312.279,73.378 h1.52
  text "X" at 329.755,73.378 h1.52
  text "V. SCORE" at 334.276,73.378 h1.52
  text "CERTIFICATION:" at 285.33,70.098 h1.52
  text "MATERIALS AND WORKMANSHIP FOR ALL PCBS" at 303.745,70.098 h1.52
  text "TO MEET OR EXCEED THE REQUIREMENTS OF:" at 303.745,67.709 h1.52
  text "X" at 294.538,64.442 h1.52
  text "ANSI IPC-A-600F CLASS ->" at 297.789,64.442 h1.52
  text "X" at 339.648,64.442 h1.52
  text "2" at 342.442,64.442 h1.52
  text "1" at 334.441,64.404 h1.52
  text "3" at 351.433,64.404 h1.52
  text "X" at 315.162,60.691 h1.52
  text "RoHS" at 318.413,60.691 h1.52
  text "OTHER" at 334.781,60.691 h1.52
  text "PER ORDER" at 344.867,60.691 h1.52
  text "ALL BOARDS MUST MEET OR EXCEED UL94-V0 REQUIREMENTS." at 286.029,56.783 h1.52
  text "PCB MUST BEAR THE UL94V-0 UL REGISTERED MATERIAL ID NUMBER" at 286.029,53.835 h1.52
  text "ADDITIONAL REQUIREMENTS:" at 285.33,49.532 h1.52
  text "MICROSECTION:" at 287.229,46.811 h1.52
  text "YES" at 310.235,46.811 h1.52
  text "REQUIRED" at 332.117,43.145 h1.52
  text "BARE BOARD ELEC. TEST:" at 287.229,43.072 h1.52
  text "NONE" at 320.395,43.072 h1.52
  text "X" at 329.12,43.072 h1.52
  text "PER ORDER" at 347.153,43.072 h1.52
  text "XX MIL VIAS REQUIRE NON-CONDUCTIVE FILL AND PLANARIZE" at 291.5,37.867 h1.5
  text "XX MIL VIAS REQUIRE CONDUCTIVE FILL AND PLANARIZE" at 291.703,35.226 h1.52
  text "OUTER XX MIL TRACES REQUIRE 50 OHM SINGLE-ENDED IMPEDANCE" at 291.678,31.076 h1.47
  text "LAYER 2 & 3 (INNER LAYERS) XX MIL WIDE, XX MIL SPACE / TRACES REQUIRE 100 OHM DIFFERENTIAL IMPEDANCE" at 291.475,25.089 h1.52
  text ".Layer_Name" at 12.116,-19.367 h1.52
M11 Gerber Information:
  lines w0.254: -9.957,-21.188 157.683,-21.188 ; -9.957,-16.023 157.734,-16.023 ; -9.957,-10.858 -9.957,-26.352 91.77,-26.352 157.734,-26.352 157.734,-10.859 -9.944,-10.859 -9.944,-26.352 30.074,-26.352 ; 52.654,-26.352 52.654,-10.859 ; 84.836,-16.023 84.836,-10.859 ; 106.172,-16.023 106.172,-10.859 ; 121.971,-26.518 121.971,-21.366
  text "ALL ARTWORK VIEWED FROM TOP SIDE" at -8.344,-14.216 h1.52
  text "BOARD #:" at 54.559,-14.216 h1.52
  text ".PRJ_Number" at 68.415,-14.216 h1.52
  text "REV:" at 89.865,-14.216 h1.52
  text ".PCB_Rev" at 97.269,-14.216 h1.52
  text "SVN REV:" at 111.15,-14.216 h1.52
  text ".VersionControl_RevNumber" at 124.003,-14.216 h1.52
  text "LAYER NAME =" at -8.344,-19.367 h1.52
  text "TID #:" at 54.559,-19.38 h1.52
  text ".TID" at 68.415,-19.38 h1.52
  text "PLOT NAME =" at -8.344,-24.596 h1.52
  text ".plot_File_Name" at 12.116,-24.596 h1.52
  text "GENERATED    :" at 54.61,-24.596 h1.52
  text ".Print_Date" at 76.695,-24.596 h1.52
  text ".Print_Time" at 95.212,-24.596 h1.52
  text "TEXAS INSTRUMENTS" at 127.33,-24.596 h1.52
M12 Stackup:
  drawing of 399 lines, arcs and shapes, not listed
  text "Layer" at 143.017,189.357 h1.52
  text "Name" at 153.428,189.357 h1.52
  text "Material" at 177.044,189.357 h1.52
  text "Thickness" at 198.882,189.357 h1.52
  text "Constant" at 215.388,189.357 h1.52
  text "Board Layer Stack" at 229.862,189.357 h1.52
  text "Top Overlay" at 153.428,186.309 h1.52
  text "Top Solder" at 153.428,183.261 h1.52
  text "Solder Resist" at 177.044,183.261 h1.52
  text "0.40mil" at 198.882,183.261 h1.52
  text "3.5" at 215.388,183.261 h1.52
  text "1" at 143.017,180.213 h1.52
  text "Layer 1" at 153.428,180.213 h1.52
  text "2.76mil" at 198.882,180.213 h1.52
  text "Dielectric 1" at 153.428,177.165 h1.52
  text "PP-006" at 177.044,177.165 h1.52
  text "2.80mil" at 198.882,177.165 h1.52
  text "4.1" at 215.388,177.165 h1.52
  text "2" at 143.017,174.117 h1.52
  text "GND 1" at 153.428,174.117 h1.52
  text "CF-004" at 177.044,174.117 h1.52
  text "2.76mil" at 198.882,174.117 h1.52
  text "Dielectric 3" at 153.428,171.069 h1.52
  text "PP-006" at 177.044,171.069 h1.52
  text "2.80mil" at 198.882,171.069 h1.52
  text "4.1" at 215.388,171.069 h1.52
  text "3" at 143.017,168.021 h1.52
  text "Layer 3" at 153.428,168.021 h1.52
  text "CF-004" at 177.044,168.021 h1.52
  text "2.76mil" at 198.882,168.021 h1.52
  text "Dielectric1" at 153.428,164.973 h1.52
  text "FR-4 High Tg" at 177.044,164.973 h1.52
  text "59.20mil" at 198.882,164.973 h1.52
  text "4.8" at 215.388,164.973 h1.52
  text "4" at 143.017,161.925 h1.52
  text "Layer 4" at 153.428,161.925 h1.52
  text "CF-004" at 177.044,161.925 h1.52
  text "2.76mil" at 198.882,161.925 h1.52
  text "Dielectric 4" at 153.428,158.877 h1.52
  text "PP-006" at 177.044,158.877 h1.52
  text "2.80mil" at 198.882,158.877 h1.52
  text "4.1" at 215.388,158.877 h1.52
  text "5" at 143.017,155.829 h1.52
  text "GND 2" at 153.428,155.829 h1.52
  text "CF-004" at 177.044,155.829 h1.52
  text "2.76mil" at 198.882,155.829 h1.52
  text "Dielectric 2" at 153.428,152.781 h1.52
  text "PP-006" at 177.044,152.781 h1.52
  text "2.80mil" at 198.882,152.781 h1.52
  text "4.1" at 215.388,152.781 h1.52
  text "6" at 143.017,149.733 h1.52
  text "Layer 6" at 153.428,149.733 h1.52
  text "2.76mil" at 198.882,149.733 h1.52
  text "Bottom Solder" at 153.428,146.685 h1.52
  text "Solder Resist" at 177.044,146.685 h1.52
  text "0.40mil" at 198.882,146.685 h1.52
  text "3.5" at 215.388,146.685 h1.52
  text "Bottom Overlay" at 153.428,143.637 h1.52
  text ".Layer_Name" at 12.116,-19.367 h1.52
M13 Component Bodies Top:
  text ".Layer_Name" at 12.116,-19.367 h1.52
M14 Component Bodies Bottom:
  text ".Layer_Name" at 12.116,-19.367 h1.52
M15 Courtyards Top:
  text ".Layer_Name" at 12.116,-19.367 h1.52
M16 Courtyards Bottom:
  text ".Layer_Name" at 12.116,-19.367 h1.52
Drill Drawing:
  circle w0.254: c157.757,96.888 r0.702
  lines w0.254: 157.055,93.379 157.406,93.379 157.406,93.028 158.108,93.028 158.108,93.379 158.459,93.379 158.459,94.081 158.108,94.081 158.108,94.432 157.406,94.432 157.406,94.081 157.055,94.081 157.055,93.379 ; 157.055,99.344 158.459,99.344 158.459,100.747 157.055,100.747 157.055,99.344 ; 157.055,102.852 157.406,102.852 157.757,102.501 158.108,102.852 158.459,102.852 158.108,103.203 158.459,103.554 158.108,103.554 157.757,103.905 157.406,103.554 157.055,103.554 157.406,103.203 157.055,102.852 ; 157.055,107.062 158.459,107.062 157.757,105.659 157.055,107.062 ; 157.055,108.817 157.757,109.168 158.459,108.817 158.108,109.518 158.459,110.22 157.757,109.869 157.055,110.22 157.406,109.518 157.055,108.817 ; 157.055,111.975 157.055,112.325 157.406,112.676 157.055,113.027 157.055,113.378 157.406,113.378 157.757,113.027 158.108,113.378 158.459,113.378 158.459,113.027 158.108,112.676 158.459,112.325 158.459,111.975 158.108,111.975 157.757,112.325 157.406,111.975 157.055,111.975 ; 157.055,115.483 157.406,115.483 157.757,115.132 158.108,115.483 158.459,115.483 158.108,115.834 158.459,116.185 158.108,116.185 157.757,116.536 157.406,116.185 157.055,116.185 157.406,115.834 157.055,115.483 ; 157.055,118.992 157.757,118.29 158.459,118.992 157.757,119.693 157.055,118.992 ; 157.055,121.448 158.459,121.448 158.459,122.851 157.055,122.851 157.055,121.448 ; 157.336,115.623 157.546,115.623 157.757,115.413 157.967,115.623 158.178,115.623 157.967,115.834 158.178,116.044 157.967,116.044 157.757,116.255 157.546,116.044 157.336,116.044 157.546,115.834 157.336,115.623 ; 157.336,121.728 158.178,121.728 158.178,122.57 157.336,122.57 157.336,121.728
  lines w0.305: 155.783,92.081 232.81,92.081 ; 155.783,123.658 232.81,123.658 ; 164.365,88.923 164.365,126.816 ; 172.797,88.923 172.797,126.816 ; 188.966,88.923 188.966,126.816 ; 195.548,88.923 195.548,126.816 ; 205.077,88.923 205.077,126.816 ; 218.423,88.923 218.423,126.816 ; 155.783,88.923 232.81,88.923 232.81,126.816 155.783,126.816 155.783,88.923
  text "Symbol" at 157.677,124.605 h1.83
  text "Quantity" at 165.312,124.605 h1.83
  text "Finished Hole Size" at 173.745,124.605 h1.83
  text "Plated" at 189.913,124.605 h1.83
  text "Hole Type" at 196.496,124.605 h1.83
  text "Drill Layer Pair" at 206.025,124.605 h1.83
  text "Hole Tolerance" at 219.37,124.605 h1.83
  text "72" at 165.312,121.448 h1.52
  text "7.87mil (0.200mm)" at 173.745,121.448 h1.52
  text "PTH" at 189.913,121.448 h1.52
  text "Round" at 196.496,121.448 h1.52
  text "Layer 1 - Layer 6" at 206.025,121.448 h1.52
  text "72" at 165.312,118.29 h1.52
  text "10.00mil (0.254mm)" at 173.745,118.29 h1.52
  text "PTH" at 189.913,118.29 h1.52
  text "Round" at 196.496,118.29 h1.52
  text "Layer 1 - Layer 6" at 206.025,118.29 h1.52
  text "352" at 165.312,115.132 h1.52
  text "12.00mil (0.305mm)" at 173.745,115.132 h1.52
  text "PTH" at 189.913,115.132 h1.52
  text "Round" at 196.496,115.132 h1.52
  text "Layer 1 - Layer 6" at 206.025,115.132 h1.52
  text "232" at 165.312,111.975 h1.52
  text "16.00mil (0.406mm)" at 173.745,111.975 h1.52
  text "PTH" at 189.913,111.975 h1.52
  text "Round" at 196.496,111.975 h1.52
  text "Layer 1 - Layer 6" at 206.025,111.975 h1.52
  text "10" at 165.312,108.817 h1.52
  text "33.07mil (0.840mm)" at 173.745,108.817 h1.52
  text "PTH" at 189.913,108.817 h1.52
  text "Round" at 196.496,108.817 h1.52
  text "Layer 1 - Layer 6" at 206.025,108.817 h1.52
  text "11" at 165.312,105.659 h1.52
  text "40.00mil (1.016mm)" at 173.745,105.659 h1.52
  text "PTH" at 189.913,105.659 h1.52
  text "Round" at 196.496,105.659 h1.52
  text "Layer 1 - Layer 6" at 206.025,105.659 h1.52
  text "11" at 165.312,102.501 h1.52
  text "40.16mil (1.020mm)" at 173.745,102.501 h1.52
  text "PTH" at 189.913,102.501 h1.52
  text "Round" at 196.496,102.501 h1.52
  text "Layer 1 - Layer 6" at 206.025,102.501 h1.52
  text "7" at 165.312,99.344 h1.52
  text "110.24mil (2.800mm)" at 173.745,99.344 h1.52
  text "PTH" at 189.913,99.344 h1.52
  text "Round" at 196.496,99.344 h1.52
  text "Layer 1 - Layer 6" at 206.025,99.344 h1.52
  text "4" at 165.312,96.186 h1.52
  text "125.98mil (3.200mm)" at 173.745,96.186 h1.52
  text "PTH" at 189.913,96.186 h1.52
  text "Round" at 196.496,96.186 h1.52
  text "Layer 1 - Layer 6" at 206.025,96.186 h1.52
  text "4" at 165.312,93.028 h1.52
  text "254.00mil (6.452mm)" at 173.745,93.028 h1.52
  text "PTH" at 189.913,93.028 h1.52
  text "Round" at 196.496,93.028 h1.52
  text "Layer 1 - Layer 6" at 206.025,93.028 h1.52
  text "775 Total" at 165.312,89.87 h1.52
  text ".Layer_Name" at 12.116,-19.367 h1.52
M17 Embedded Cavity:
  text ".Layer_Name" at 12.116,-19.367 h1.52
M18 Embedded Assembly:
  text ".Layer_Name" at 12.116,-19.367 h1.52
M19 Embedded Keepout:
  text ".Layer_Name" at 12.116,-19.367 h1.52

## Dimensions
-2.54,-7.722 to 22.86,-7.722 on M2 Board Dimensions
-2.54,2.438 to 121.92,0 on M2 Board Dimensions
6.883,0.051 to 108.357,0.062 on M2 Board Dimensions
